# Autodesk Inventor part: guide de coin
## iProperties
Shininess: 64.0
Length Units: 11269
Angle Units: 11279
Time Units: 11290
Mass Units: 11283
Length Display Precision: 3
Angle Display Precision: 2
Compacted: True
Part Number: guide de coin
Document SubType Name: Modeling
Created: 2004-12
Material: Par défaut
Designer: LEGERET Philippe
Density: 0.0
Volumn: 0.0
Area: 0.0
PropertySet Name: Model Information
Control State: 0
Master: False
Checked Out: False
Author: LEGERET Philippe
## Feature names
1. Extrusion1
2. Extrusion2
3. Extrusion3
4. Perçage1 [Hole]
5. Perçage2 [Hole]
6. Perçage3 [Hole]
7. Réseau circulaire1 [Circular Pattern]
8. Extrusion4
9. Symétrie1 [Mirror]
10. Perçage4 [Hole]
11. Symétrie2 [Mirror]
12. Extrusion5
13. Extrusion6
